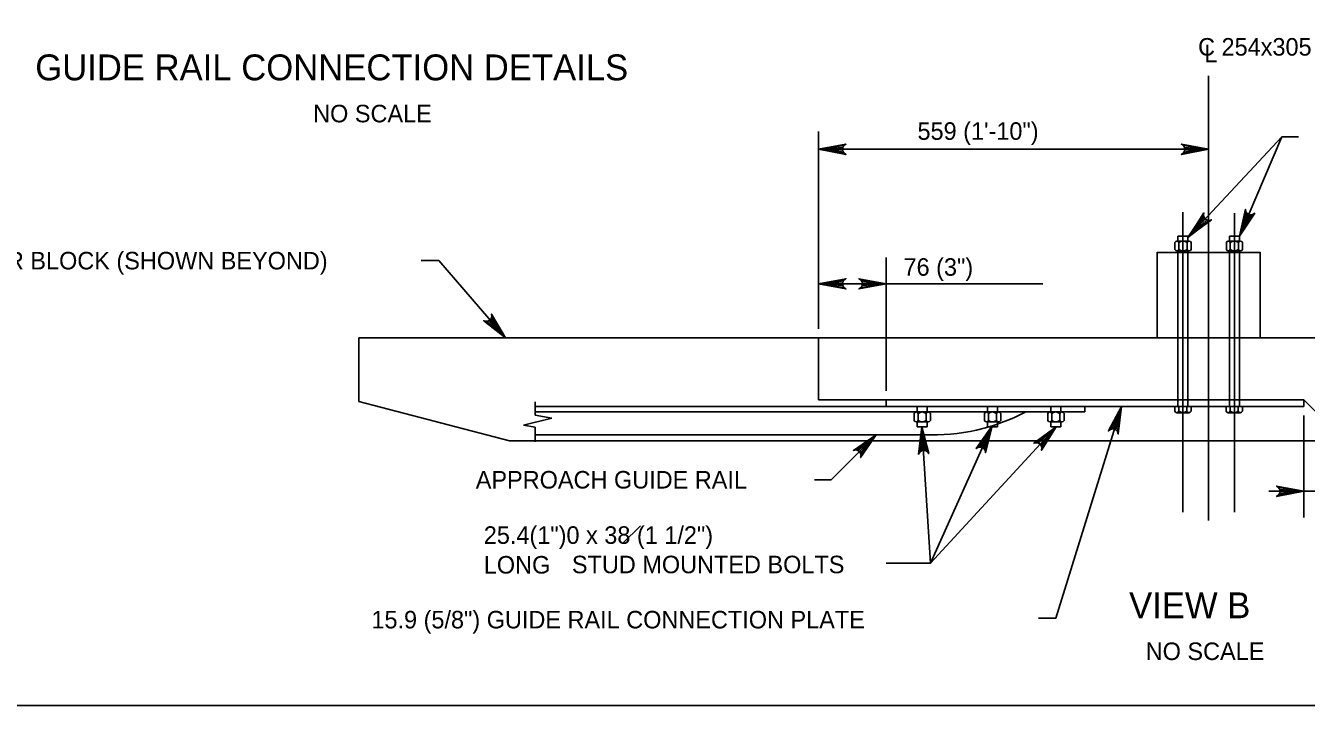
# Model space of a CAD drawing. Extents: x 0 to 36.3, y -66 to 0.
# Drawn here: x 4.42 to 13.18, y -21.25 to -16.6 of the extents above; entities that cross this region are included whole.
import ezdxf

# ---------------------------------------------------------------- set-up
doc = ezdxf.new("R2010")
doc.units = 0
for name, color, linetype in [('1', 7, 'Continuous'), ('2', 7, 'Continuous'), ('3', 7, 'Continuous')]:
    doc.layers.add(name, color=color, linetype=linetype)

msp = doc.modelspace()

# ---------------------------------------------------------------- linework, layer by layer
at = {"layer": '1'}
msp.add_lwpolyline([(1.75, -21.25), (33.25, -21.25), (33.25, -0.75), (1.75, -0.75)], close=True, dxfattribs=at)
at = {"layer": '2'}
for p, q in [((12.375, -18.0392), (13.0098, -17.3584)), ((12.7186, -18.0397), (13.0098, -17.3584)), ((12.2988, -18.0728), (12.2988, -18.0392)), ((12.2988, -18.0392), (12.3673, -18.0392)), ((12.3673, -18.0728), (12.3673, -18.0392)), ((12.6503, -18.0392), (12.7187, -18.0392)), ((12.6503, -18.0728), (12.6503, -18.0392)), ((12.7187, -18.0728), (12.7187, -18.0392)), ((12.2784, -18.0827), (12.2784, -18.1303)), ((12.2913, -18.0728), (12.3757, -18.0728)), ((12.3052, -18.1303), (12.3052, -18.0827)), ((12.3608, -18.1303), (12.3608, -18.0827)), ((12.3896, -18.0827), (12.3896, -18.1303)), ((12.6299, -18.0827), (12.6299, -18.1303)), ((12.6428, -18.0728), (12.7272, -18.0728)), ((12.6567, -18.1303), (12.6567, -18.0827)), ((12.7123, -18.1303), (12.7123, -18.0827)), ((12.7411, -18.0827), (12.7411, -18.1303)), ((12.1573, -18.7351), (12.1573, -18.1492)), ((12.1573, -18.1498), (12.8602, -18.1498)), ((12.2913, -18.1402), (12.3757, -18.1402)), ((12.2988, -19.2051), (12.2988, -18.1402)), ((12.3673, -19.2051), (12.3673, -18.1402)), ((12.6428, -18.1402), (12.7272, -18.1402)), ((12.6503, -19.2051), (12.6503, -18.1402)), ((12.7187, -19.2051), (12.7187, -18.1402)), ((12.8602, -18.7351), (12.8602, -18.1492)), ((6.6988, -18.7355), (9.842, -18.7355)), ((6.6988, -18.7355), (6.6988, -19.1706)), ((9.842, -18.7351), (14.7836, -18.7351)), ((9.842, -18.7351), (9.842, -19.1587)), ((6.6988, -19.1706), (7.728, -19.4385)), ((7.9042, -19.1717), (7.9042, -19.2635)), ((9.842, -19.1587), (13.1592, -19.1587)), ((10.3038, -19.1587), (10.3038, -19.204)), ((13.439, -19.4385), (13.1592, -19.1587)), ((13.1592, -19.1587), (13.1592, -19.204)), ((7.9042, -19.204), (13.1592, -19.204)), ((7.9042, -19.2418), (11.6631, -19.2418)), ((7.9042, -19.2635), (8.0175, -19.2843)), ((10.4953, -19.2993), (10.4953, -19.2517)), ((10.5083, -19.2418), (10.5925, -19.2418)), ((10.5157, -19.204), (10.5157, -19.2418)), ((10.5221, -19.2517), (10.5221, -19.2993)), ((10.5777, -19.2517), (10.5777, -19.2993)), ((10.5841, -19.204), (10.5841, -19.2418)), ((10.6064, -19.2993), (10.6064, -19.2517)), ((10.9759, -19.2993), (10.9759, -19.2517)), ((10.9887, -19.2418), (11.0731, -19.2418)), ((10.9962, -19.204), (10.9962, -19.2418)), ((11.0027, -19.2517), (11.0027, -19.2993)), ((11.0582, -19.2517), (11.0582, -19.2993)), ((11.0647, -19.204), (11.0647, -19.2418)), ((11.087, -19.2993), (11.087, -19.2517)), ((11.409, -19.2993), (11.409, -19.2517)), ((11.4219, -19.2418), (11.5062, -19.2418)), ((11.4294, -19.204), (11.4294, -19.2418)), ((11.4358, -19.2517), (11.4358, -19.2993)), ((11.4913, -19.2517), (11.4913, -19.2993)), ((11.4977, -19.204), (11.4977, -19.2418)), ((11.5202, -19.2993), (11.5202, -19.2517)), ((11.6631, -19.204), (11.6631, -19.2418)), ((12.2775, -19.2051), (12.2775, -19.2368)), ((12.3886, -19.2051), (12.2775, -19.2051)), ((12.2904, -19.2467), (12.3747, -19.2467)), ((12.3042, -19.2368), (12.3042, -19.2051)), ((12.3598, -19.2368), (12.3598, -19.2051)), ((12.3886, -19.2051), (12.3886, -19.2368)), ((12.7401, -19.2051), (12.6289, -19.2051)), ((12.6289, -19.2051), (12.6289, -19.2368)), ((12.6418, -19.2467), (12.7262, -19.2467)), ((12.6557, -19.2368), (12.6557, -19.2051)), ((12.7113, -19.2368), (12.7113, -19.2051)), ((12.7401, -19.2051), (12.7401, -19.2368)), ((8.0175, -19.2843), (7.8238, -19.3326)), ((7.8238, -19.3326), (7.9042, -19.346)), ((7.9042, -19.346), (7.9042, -19.4459)), ((10.5083, -19.3092), (10.5925, -19.3092)), ((10.5157, -19.3092), (10.5157, -19.3427)), ((10.5157, -19.3427), (10.5841, -19.3427)), ((10.5841, -19.3092), (10.5841, -19.3427)), ((10.9887, -19.3092), (11.0731, -19.3092)), ((10.9962, -19.3092), (10.9962, -19.3427)), ((10.9962, -19.3427), (11.0647, -19.3427)), ((11.0647, -19.3092), (11.0647, -19.3427)), ((11.4219, -19.3092), (11.5062, -19.3092)), ((11.4294, -19.3092), (11.4294, -19.3427)), ((11.4294, -19.3427), (11.4977, -19.3427)), ((11.4977, -19.3092), (11.4977, -19.3427)), ((7.728, -19.4385), (13.439, -19.4385)), ((10.5647, -19.3976), (7.9042, -19.3976))]:
    msp.add_line(p, q, dxfattribs=at)
for points in [[(12.4637, -17.9735), (12.4344, -17.9462), (12.3673, -18.0476)], [(12.7843, -17.9368), (12.7475, -17.9211), (12.7187, -18.0392)]]:
    msp.add_lwpolyline(points, close=True, dxfattribs=at)
for centre, radius, start, end in [((12.2918, -18.0869), 0.014, 17.45181, 162.54819), ((12.333, -18.1171), 0.0442, 51.05, 128.95), ((12.3752, -18.0883), 0.0154, 91.82706, 158.71306), ((12.3752, -18.0883), 0.0154, 21.28694, 91.82706), ((12.6433, -18.0869), 0.014, 17.45181, 162.54819), ((12.6845, -18.1171), 0.0442, 51.05, 128.95), ((12.7266, -18.0883), 0.0154, 91.82706, 158.71306), ((12.7266, -18.0883), 0.0154, 21.28694, 91.82706), ((12.2918, -18.1261), 0.014, 197.45181, 342.54819), ((12.333, -18.096), 0.0442, 231.05, 308.95), ((12.3752, -18.1247), 0.0154, 201.28694, 268.17294), ((12.3752, -18.1247), 0.0154, 268.17294, 338.71305), ((12.6433, -18.1261), 0.014, 197.45181, 342.54819), ((12.6845, -18.096), 0.0442, 231.05, 308.95), ((12.7266, -18.1247), 0.0154, 201.28694, 268.17294), ((12.7266, -18.1247), 0.0154, 268.17294, 338.71305), ((10.5087, -19.2559), 0.014, 17.45181, 162.54819), ((10.5498, -19.2861), 0.0442, 51.05, 128.95), ((10.6223, -18.034), 1.3648, 267.57896, 297.74747), ((10.592, -19.2573), 0.0154, 91.82706, 158.71306), ((10.592, -19.2573), 0.0154, 21.28694, 91.82706), ((10.9892, -19.2559), 0.014, 17.45181, 162.54819), ((11.0304, -19.2861), 0.0442, 51.05, 128.95), ((11.0726, -19.2573), 0.0154, 91.82706, 158.71306), ((11.0726, -19.2573), 0.0154, 21.28694, 91.82706), ((11.4224, -19.2559), 0.014, 17.45181, 162.54819), ((11.4635, -19.2861), 0.0442, 51.05, 128.95), ((11.5057, -19.2573), 0.0154, 91.82706, 158.71306), ((11.5057, -19.2573), 0.0154, 21.28694, 91.82706), ((12.2908, -19.2327), 0.014, 197.45181, 342.54819), ((12.332, -19.2025), 0.0442, 231.05, 308.95), ((12.3742, -19.2313), 0.0154, 201.28694, 268.17294), ((12.3742, -19.2313), 0.0154, 268.17294, 338.71305), ((12.6423, -19.2327), 0.014, 197.45181, 342.54819), ((12.6835, -19.2025), 0.0442, 231.05, 308.95), ((12.7257, -19.2313), 0.0154, 201.28694, 268.17294), ((12.7257, -19.2313), 0.0154, 268.17294, 338.71305), ((10.5087, -19.2951), 0.014, 197.45181, 342.54819), ((10.5498, -19.265), 0.0442, 231.05, 308.95), ((10.592, -19.2937), 0.0154, 201.28694, 268.17294), ((10.592, -19.2937), 0.0154, 268.17294, 338.71305), ((10.9892, -19.2951), 0.014, 197.45181, 342.54819), ((11.0304, -19.265), 0.0442, 231.05, 308.95), ((11.0726, -19.2937), 0.0154, 201.28694, 268.17294), ((11.0726, -19.2937), 0.0154, 268.17294, 338.71305), ((11.4224, -19.2951), 0.014, 197.45181, 342.54819), ((11.4635, -19.265), 0.0442, 231.05, 308.95), ((11.5057, -19.2937), 0.0154, 201.28694, 268.17294), ((11.5057, -19.2937), 0.0154, 268.17294, 338.71305)]:
    msp.add_arc(centre, radius, start, end, dxfattribs=at)
at = {"layer": '3'}
for p, q in [((12.5087, -16.9413), (12.5088, -19.9852)), ((9.842, -18.6726), (9.842, -17.3218)), ((13.0098, -17.3584), (13.1223, -17.3584)), ((9.842, -17.4443), (12.5087, -17.4443)), ((9.962, -17.4443), (10.082, -17.4443)), ((12.333, -19.9282), (12.333, -17.8749)), ((12.6845, -19.9282), (12.6845, -17.8802)), ((7.2444, -18.2062), (7.1244, -18.2062)), ((7.7005, -18.7355), (7.2444, -18.2062)), ((10.3038, -19.0962), (10.3038, -18.1845)), ((9.842, -18.3645), (11.3757, -18.3645)), ((10.082, -18.3645), (10.2465, -18.3645)), ((11.9117, -19.204), (11.4642, -20.6524)), ((13.1592, -19.2665), (13.1592, -19.9642)), ((10.5481, -19.3427), (10.6059, -20.2758)), ((11.028, -19.3371), (10.6059, -20.2758)), ((11.4665, -19.3427), (10.6059, -20.2758)), ((10.236, -19.3976), (9.9269, -19.7056)), ((9.9269, -19.7056), (9.8144, -19.7056)), ((13.0392, -19.7843), (12.9192, -19.7843)), ((13.0833, -19.7843), (14.6616, -19.7843)), ((8.5015, -20.1428), (8.6228, -20.0215)), ((10.6059, -20.2758), (10.3047, -20.2758)), ((11.4642, -20.6524), (11.3442, -20.6524))]:
    msp.add_line(p, q, dxfattribs=at)
for points in [[(9.842, -17.4443), (10.0284, -17.4094), (10.0141, -17.4193), (10.0067, -17.4318), (10.0045, -17.4443), (10.0067, -17.4568), (10.0141, -17.4693), (10.0284, -17.4793), (9.842, -17.4443), (10.0141, -17.4693), (10.0067, -17.4568), (9.842, -17.4443), (10.0045, -17.4443), (10.0067, -17.4318), (9.842, -17.4443), (10.0141, -17.4193)], [(12.5087, -17.4443), (12.3223, -17.4793), (12.3367, -17.4693), (12.3441, -17.4568), (12.3462, -17.4443), (12.3441, -17.4318), (12.3367, -17.4193), (12.3223, -17.4094), (12.5087, -17.4443), (12.3367, -17.4193), (12.3441, -17.4318), (12.5087, -17.4443), (12.3462, -17.4443), (12.3441, -17.4568), (12.5087, -17.4443), (12.3367, -17.4693)], [(12.7186, -18.0397), (12.7598, -17.8545), (12.7632, -17.8717), (12.7718, -17.8833), (12.7825, -17.8902), (12.7948, -17.8932), (12.8092, -17.8913), (12.824, -17.882), (12.7186, -18.0397), (12.8092, -17.8913), (12.7948, -17.8932), (12.7186, -18.0397), (12.7825, -17.8902), (12.7718, -17.8833), (12.7186, -18.0397), (12.7632, -17.8717)], [(12.375, -18.0392), (12.4766, -17.8791), (12.4741, -17.8963), (12.4782, -17.9103), (12.4858, -17.9204), (12.4964, -17.9273), (12.5106, -17.9305), (12.5277, -17.9267), (12.375, -18.0392), (12.5106, -17.9305), (12.4964, -17.9273), (12.375, -18.0392), (12.4858, -17.9204), (12.4782, -17.9103), (12.375, -18.0392), (12.4741, -17.8963)], [(9.842, -18.3645), (10.0284, -18.3296), (10.0141, -18.3395), (10.0067, -18.352), (10.0045, -18.3645), (10.0067, -18.377), (10.0141, -18.3895), (10.0284, -18.3994), (9.842, -18.3645), (10.0141, -18.3895), (10.0067, -18.377), (9.842, -18.3645), (10.0045, -18.3645), (10.0067, -18.352), (9.842, -18.3645), (10.0141, -18.3395)], [(10.3038, -18.3645), (10.1174, -18.3994), (10.1318, -18.3895), (10.1392, -18.377), (10.1413, -18.3645), (10.1392, -18.352), (10.1318, -18.3395), (10.1174, -18.3296), (10.3038, -18.3645), (10.1318, -18.3395), (10.1392, -18.352), (10.3038, -18.3645), (10.1413, -18.3645), (10.1392, -18.377), (10.3038, -18.3645), (10.1318, -18.3895)], [(7.7005, -18.7355), (7.5523, -18.6171), (7.5692, -18.6215), (7.5836, -18.6189), (7.5944, -18.6124), (7.6025, -18.6026), (7.6072, -18.5888), (7.6053, -18.5715), (7.7005, -18.7355), (7.6072, -18.5888), (7.6025, -18.6026), (7.7005, -18.7355), (7.5944, -18.6124), (7.5836, -18.6189), (7.7005, -18.7355), (7.5692, -18.6215)], [(11.9117, -19.204), (11.8901, -19.3924), (11.8848, -19.3758), (11.875, -19.365), (11.8637, -19.3592), (11.8512, -19.3576), (11.837, -19.361), (11.8232, -19.3718), (11.9117, -19.204), (11.837, -19.361), (11.8512, -19.3576), (11.9117, -19.204), (11.8637, -19.3592), (11.875, -19.365), (11.9117, -19.204), (11.8848, -19.3758)], [(10.5481, -19.3427), (10.5945, -19.5266), (10.5837, -19.5128), (10.5708, -19.5062), (10.5582, -19.5048), (10.5457, -19.5077), (10.5337, -19.5159), (10.5247, -19.5309), (10.5481, -19.3427), (10.5337, -19.5159), (10.5457, -19.5077), (10.5481, -19.3427), (10.5582, -19.5048), (10.5708, -19.5062), (10.5481, -19.3427), (10.5837, -19.5128)], [(11.028, -19.3371), (10.9834, -19.5214), (10.9802, -19.5042), (10.9719, -19.4923), (10.9613, -19.4853), (10.9491, -19.4821), (10.9347, -19.4838), (10.9197, -19.4928), (11.028, -19.3371), (10.9347, -19.4838), (10.9491, -19.4821), (11.028, -19.3371), (10.9613, -19.4853), (10.9719, -19.4923), (11.028, -19.3371), (10.9802, -19.5042)], [(11.4665, -19.3427), (11.3658, -19.5034), (11.3682, -19.4861), (11.3641, -19.4722), (11.3563, -19.4621), (11.3457, -19.4552), (11.3315, -19.4522), (11.3144, -19.456), (11.4665, -19.3427), (11.3315, -19.4522), (11.3457, -19.4552), (11.4665, -19.3427), (11.3563, -19.4621), (11.3641, -19.4722), (11.4665, -19.3427), (11.3682, -19.4861)], [(10.236, -19.3976), (10.1287, -19.5539), (10.1318, -19.5367), (10.1282, -19.5227), (10.1209, -19.5122), (10.1106, -19.5049), (10.0965, -19.5013), (10.0793, -19.5044), (10.236, -19.3976), (10.0965, -19.5013), (10.1106, -19.5049), (10.236, -19.3976), (10.1209, -19.5122), (10.1282, -19.5227), (10.236, -19.3976), (10.1318, -19.5367)], [(13.1592, -19.7843), (12.9727, -19.8192), (12.9871, -19.8092), (12.9945, -19.7967), (12.9967, -19.7843), (12.9945, -19.7718), (12.9871, -19.7592), (12.9727, -19.7493), (13.1592, -19.7843), (12.9871, -19.7592), (12.9945, -19.7718), (13.1592, -19.7843), (12.9967, -19.7843), (12.9945, -19.7967), (13.1592, -19.7843), (12.9871, -19.8092)]]:
    msp.add_lwpolyline(points, dxfattribs=at)
for points in [[(9.962, -17.4643), (9.962, -17.4243), (9.842, -17.4443)], [(12.3887, -17.4643), (12.3887, -17.4243), (12.5087, -17.4443)], [(9.962, -18.3845), (9.962, -18.3445), (9.842, -18.3645)], [(10.1838, -18.3845), (10.1838, -18.3445), (10.3038, -18.3645)], [(7.6373, -18.6316), (7.607, -18.6577), (7.7005, -18.7355)], [(11.8572, -19.3127), (11.8953, -19.3246), (11.9117, -19.204)], [(10.5356, -19.4637), (10.5755, -19.4612), (10.5481, -19.3427)], [(10.958, -19.4439), (10.9945, -19.4603), (11.0254, -19.3427)], [(11.3703, -19.4173), (11.3997, -19.4445), (11.4664, -19.3427)], [(10.143, -19.4638), (10.1695, -19.4903), (10.2358, -19.3976)], [(13.0392, -19.7643), (13.0392, -19.8042), (13.1592, -19.7843)]]:
    msp.add_lwpolyline(points, close=True, dxfattribs=at)

# ---------------------------------------------------------------- texts
at = {"layer": '2'}
for s, height, p in [('GUIDE RAIL CONNECTION DETAILS', 0.177167, (4.4851, -16.9722)), ('VIEW B', 0.17717, (11.9648, -20.6535))]:
    msp.add_text(s, height=height, dxfattribs=at).set_placement(p)
at = {"layer": '3'}
for s, p in [('C 254x305 (10"x12")POST', (12.4365, -16.803)), ('L', (12.4792, -16.8486)), ('NO SCALE', (6.3853, -17.2596)), ('559 (1\'-10")', (10.5179, -17.3794)), ('SCUPPER BLOCK (SHOWN BEYOND)', (3.6313, -18.2662)), ('76 (3")', (10.4223, -18.3096)), ('APPROACH GUIDE RAIL', (7.4972, -19.7657)), ('25.4(1")0 x 38 (1 1/2")', (7.5522, -20.1443)), ('LONG', (7.5522, -20.3477)), ('STUD MOUNTED BOLTS', (8.1548, -20.3456)), ('15.9 (5/8") GUIDE RAIL CONNECTION PLATE', (6.7837, -20.7231)), ('NO SCALE', (12.0783, -20.9394))]:
    msp.add_text(s, height=0.12, dxfattribs=at).set_placement(p)

doc.saveas('drawing.dxf')
